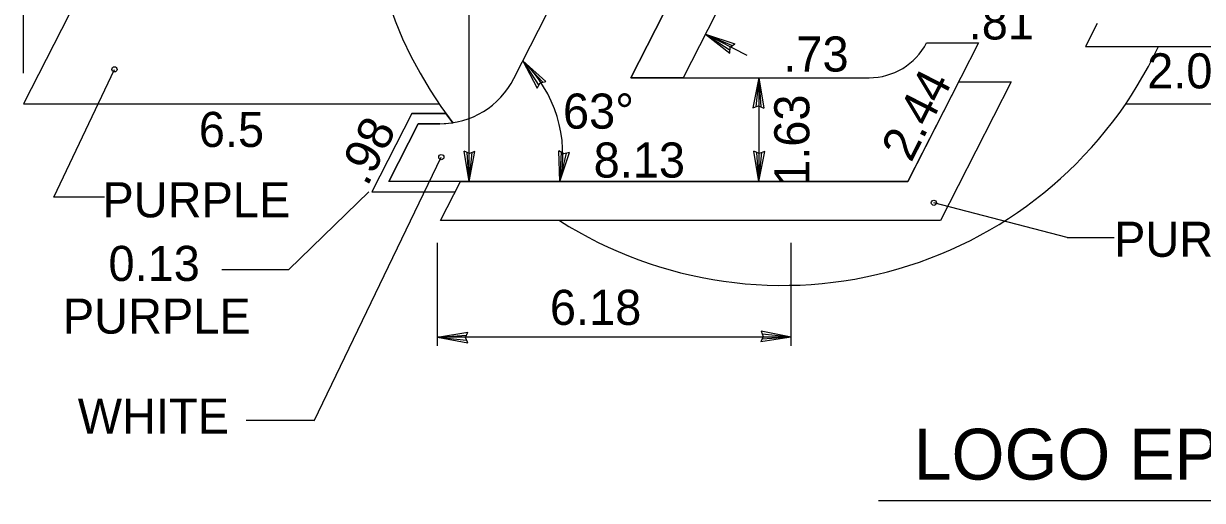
# Model space of a CAD drawing. Extents: x 10268197 to 10269179, y 2141503 to 2142677.
# Drawn here: x 10268592.24 to 10268612.19, y 2142145.29 to 2142153.36 of the extents above; entities that cross this region are included whole.
import ezdxf

# ---------------------------------------------------------------- set-up
doc = ezdxf.new("R2010")
doc.units = 0
for name, color, linetype in [('1', 7, 'Continuous'), ('21', 7, 'Continuous'), ('Default', 7, 'Continuous')]:
    doc.layers.add(name, color=color, linetype=linetype)

msp = doc.modelspace()

# ---------------------------------------------------------------- linework, layer by layer
at = {"layer": '1'}
for p, q in [((10268592.239, 2142152.526), (10268592.239, 2142165.546)), ((10268599.779, 2142150.689), (10268599.779, 2142161.234)), ((10268602.517, 2142152.447), (10268603.972, 2142155.302)), ((10268604.523, 2142154.642), (10268603.404, 2142152.447)), ((10268604.487, 2142152.825), (10268603.78, 2142153.185)), ((10268603.78, 2142153.185), (10268604.275, 2142153.024)), ((10268603.78, 2142153.185), (10268604.19, 2142152.865)), ((10268603.78, 2142153.185), (10268604.195, 2142152.916)), ((10268603.78, 2142153.185), (10268604.234, 2142152.993)), ((10268604.19, 2142152.865), (10268604.198, 2142152.963)), ((10268604.198, 2142152.963), (10268604.275, 2142153.024)), ((10268600.689, 2142152.731), (10268601.077, 2142152.384)), ((10268600.689, 2142152.731), (10268600.934, 2142152.272)), ((10268600.689, 2142152.731), (10268600.959, 2142152.317)), ((10268600.689, 2142152.731), (10268601.027, 2142152.371)), ((10268592.754, 2142150.424), (10268593.777, 2142152.589)), ((10268600.934, 2142152.272), (10268600.981, 2142152.359)), ((10268600.981, 2142152.359), (10268601.077, 2142152.384)), ((10268603.404, 2142152.447), (10268602.517, 2142152.447)), ((10268604.683, 2142152.447), (10268604.584, 2142151.936)), ((10268604.683, 2142152.447), (10268604.632, 2142151.956)), ((10268604.683, 2142152.447), (10268604.683, 2142150.689)), ((10268604.683, 2142152.447), (10268604.765, 2142151.933)), ((10268604.683, 2142152.447), (10268604.717, 2142151.955)), ((10268607.205, 2142150.689), (10268608.066, 2142152.379)), ((10268608.954, 2142152.379), (10268607.757, 2142150.03)), ((10268608.066, 2142152.379), (10268608.954, 2142152.379)), ((10268604.584, 2142151.936), (10268604.676, 2142151.974)), ((10268604.676, 2142151.974), (10268604.765, 2142151.933)), ((10268597.156, 2142146.641), (10268599.309, 2142151.104)), ((10268599.779, 2142150.689), (10268599.697, 2142151.203)), ((10268599.787, 2142151.162), (10268599.697, 2142151.203)), ((10268599.779, 2142150.689), (10268599.744, 2142151.181)), ((10268599.779, 2142150.689), (10268599.878, 2142151.2)), ((10268599.779, 2142150.689), (10268599.83, 2142151.18)), ((10268599.878, 2142151.2), (10268599.787, 2142151.162)), ((10268601.317, 2142150.689), (10268601.299, 2142151.209)), ((10268601.383, 2142151.158), (10268601.299, 2142151.209)), ((10268601.317, 2142150.689), (10268601.478, 2142151.184)), ((10268601.317, 2142150.689), (10268601.343, 2142151.182)), ((10268601.317, 2142150.689), (10268601.427, 2142151.171)), ((10268601.478, 2142151.184), (10268601.383, 2142151.158)), ((10268604.683, 2142150.689), (10268604.601, 2142151.203)), ((10268604.691, 2142151.162), (10268604.601, 2142151.203)), ((10268604.683, 2142150.689), (10268604.649, 2142151.181)), ((10268604.683, 2142150.689), (10268604.782, 2142151.2)), ((10268604.683, 2142150.689), (10268604.734, 2142151.18)), ((10268604.782, 2142151.2), (10268604.691, 2142151.162)), ((10268599.297, 2142150.03), (10268599.633, 2142150.689)), ((10268599.633, 2142150.689), (10268607.205, 2142150.689)), ((10268596.73, 2142149.2), (10268598.084, 2142150.513)), ((10268593.61, 2142150.424), (10268592.754, 2142150.424)), ((10268609.901, 2142149.741), (10268607.645, 2142150.331)), ((10268607.757, 2142150.03), (10268599.297, 2142150.03)), ((10268609.901, 2142149.741), (10268610.696, 2142149.741)), ((10268599.246, 2142147.908), (10268599.246, 2142149.653)), ((10268605.232, 2142147.908), (10268605.232, 2142149.653)), ((10268595.595, 2142149.2), (10268596.73, 2142149.2)), ((10268605.232, 2142148.056), (10268599.246, 2142148.056)), ((10268596.005, 2142146.649), (10268597.156, 2142146.649))]:
    msp.add_line(p, q, dxfattribs=at)
for centre in [(10268593.777, 2142152.589), (10268599.309, 2142151.104), (10268607.645, 2142150.331)]:
    msp.add_circle(centre, 0.0439, dxfattribs=at)
msp.add_arc((10268599.168, 2142151.145), 2.197, 348.03, 46.2026, dxfattribs=at)
at = {"layer": '21'}
for p, q in [((10268599.246, 2142148.056), (10268599.76, 2142148.138)), ((10268599.246, 2142148.056), (10268599.739, 2142148.091)), ((10268599.72, 2142148.049), (10268599.76, 2142148.138)), ((10268605.232, 2142148.056), (10268604.721, 2142148.155)), ((10268604.721, 2142148.155), (10268604.758, 2142148.064)), ((10268605.232, 2142148.056), (10268604.741, 2142148.108)), ((10268599.246, 2142148.056), (10268599.757, 2142147.957)), ((10268599.246, 2142148.056), (10268599.738, 2142148.005)), ((10268599.757, 2142147.957), (10268599.72, 2142148.049)), ((10268604.758, 2142148.064), (10268604.718, 2142147.975)), ((10268605.232, 2142148.056), (10268604.718, 2142147.975)), ((10268605.232, 2142148.056), (10268604.74, 2142148.022)), ((10268606.71, 2142145.291), (10268616.551, 2142145.291))]:
    msp.add_line(p, q, dxfattribs=at)
at = {"layer": 'Default'}
for p, q in [((10268600.538, 2142152.436), (10268604.184, 2142159.592)), ((10268603.972, 2142155.302), (10268602.517, 2142152.447)), ((10268602.517, 2142152.447), (10268603.972, 2142155.302)), ((10268604.523, 2142154.642), (10268603.404, 2142152.447)), ((10268593.135, 2142153.765), (10268592.239, 2142152.007)), ((10268610.406, 2142153.364), (10268610.209, 2142152.974)), ((10268608.402, 2142153.038), (10268607.205, 2142150.689)), ((10268607.523, 2142153.038), (10268608.402, 2142153.038)), ((10268610.209, 2142152.974), (10268612.405, 2142152.974)), ((10268602.517, 2142152.447), (10268606.548, 2142152.447)), ((10268603.404, 2142152.447), (10268602.517, 2142152.447)), ((10268607.205, 2142150.689), (10268608.066, 2142152.379)), ((10268608.954, 2142152.379), (10268607.757, 2142150.03)), ((10268608.066, 2142152.379), (10268608.954, 2142152.379)), ((10268592.239, 2142152.007), (10268599.268, 2142152.007)), ((10268610.892, 2142152.007), (10268632.66, 2142152.007)), ((10268598.809, 2142151.844), (10268598.132, 2142150.513)), ((10268598.809, 2142151.844), (10268599.383, 2142151.844)), ((10268598.419, 2142150.689), (10268598.917, 2142151.668)), ((10268598.917, 2142151.668), (10268598.419, 2142150.689)), ((10268598.917, 2142151.668), (10268599.286, 2142151.668)), ((10268599.286, 2142151.668), (10268598.917, 2142151.668)), ((10268607.205, 2142150.689), (10268598.419, 2142150.689)), ((10268599.297, 2142150.03), (10268599.633, 2142150.689)), ((10268599.633, 2142150.689), (10268607.205, 2142150.689)), ((10268598.132, 2142150.513), (10268599.543, 2142150.513)), ((10268607.757, 2142150.03), (10268599.297, 2142150.03))]:
    msp.add_line(p, q, dxfattribs=at)
msp.add_lwpolyline([(10268599.383, 2142151.844), (10268598.809, 2142151.844), (10268598.132, 2142150.513), (10268599.543, 2142150.513), (10268599.633, 2142150.689), (10268598.419, 2142150.689), (10268598.917, 2142151.668), (10268599.286, 2142151.668), (10268599.502, 2142151.685)], close=True, dxfattribs=at)
for centre, radius, start, end in [((10268605.081, 2142155.962), 7.03, 48.5904, 217.4725), ((10268605.081, 2142155.962), 7.03, 237.5383, 334.8493), ((10268606.548, 2142153.545), 1.098, 270, 332.5096), ((10268599.286, 2142153.074), 1.406, 270, 332.9991)]:
    msp.add_arc(centre, radius, start, end, dxfattribs=at)

# ---------------------------------------------------------------- texts
at = {"layer": '1'}
for s, height, p in [('.81', 0.5942, (10268608.235, 2142153.095)), ('.73', 0.5942, (10268605.098, 2142152.552)), ('2.03', 0.5942, (10268611.255, 2142152.267)), ('63°', 0.5942, (10268601.368, 2142151.585)), ('6.5', 0.5942, (10268595.205, 2142151.275)), ('8.13', 0.5942, (10268601.887, 2142150.757)), ('PURPLE', 0.5942, (10268593.574, 2142150.084)), ('PURPLE', 0.5942, (10268610.695, 2142149.416)), ('0.13', 0.5942, (10268593.676, 2142149.007)), ('PURPLE', 0.5942, (10268592.904, 2142148.115)), ('6.18', 0.5942, (10268601.147, 2142148.263)), ('WHITE', 0.5942, (10268593.156, 2142146.422)), ('LOGO EP-6.5R', 0.86053, (10268607.305, 2142145.644))]:
    msp.add_text(s, height=height, dxfattribs=at).set_placement(p)
for s, rotation, p in [('2.44', 63, (10268607.26, 2142150.998)), ('1.63', 90, (10268605.538, 2142150.617)), ('.98', 63, (10268598.055, 2142150.592))]:
    msp.add_text(s, height=0.5942, rotation=rotation, dxfattribs=at).set_placement(p)

doc.saveas('drawing.dxf')
